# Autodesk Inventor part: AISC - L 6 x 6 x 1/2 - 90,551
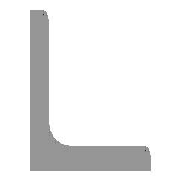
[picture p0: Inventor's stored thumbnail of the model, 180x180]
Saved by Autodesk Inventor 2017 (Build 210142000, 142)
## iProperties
Created: 2016-02
Part Number: AISC - L 6 x 6 x 1/2 - 90,551
Material: Stal, miękka
Description: Kątownik
Document SubType Name: Modeling
Standard: ANSI
Designer: X
Standards Organization: ANSI
Language: pl-PL
Size Designation: L 6 x 6 x 1/2
Categories: <MemberInstance><Categories><Category DisplayName="Kształtowniki konstrukcyjne" InternalName="089c4875-fa83-4c05-b084-43b9cc11f5ed" Mnemonic="GRDR"><CategoryPar
Stock Number: L 6 x 6 x 1/2
Density: 7.85 g/cm^3
Appearance: Częściowo polerowana
_CCFamilyMember: 47
_CCFamilyDisplayName: ANSI L (Kątownik równoramienny) - Kątownik — Rozmiary w nawiasach zostały wycofane
_FrameMemberDoc: Frame Member File
_Version: 15.0.0
_GetPNFromCC: 1
G_L: 2300,000 mm
G_W: 152,400 mm
G_H: 152,400 mm
IsCustomPart: 1
Author: X
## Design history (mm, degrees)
node "Płaszczyzna początkowa"
node "Płaszczyzna końcowa"
sketch "Szkic"
  geometry: L1 (152.4, 0)-(0, 0); L2 (0, 0)-(0, 152.4); L3 (0, 152.4)-(6.35, 152.4); L4 (12.7, 146.05)-(12.7, 25.4); L5 (25.4, 12.7)-(146.05, 12.7); L6 (152.4, 6.35)-(152.4, 0); L7 (0, -11.041)-(0, 31.538); L8 (-11.041, 0)-(31.538, 0); L9 (0, 186.666)-(0, -43.993) reference; L10 (-43.993, 0)-(186.666, 0) reference; A1 r 12.7 centre (25.4, 25.4) between (12.7, 25.4) and (25.4, 12.7); A2 r 6.35 centre (6.35, 146.05) between (12.7, 146.05) and (6.35, 152.4); A3 r 6.35 centre (146.05, 6.35) between (152.4, 6.35) and (146.05, 12.7); 3 further points
  constraints: 16 end point, 6 point on circle, 6 point on line, 6 tangent, 4 parallel, 3 centre point, 2 collinear, 1 equal radius, 1 horizontal, 1 perpendicular
  dimensions: "d0" = 152.4 distance between parallel lines of L6 L2 (= G_H); "d1" = 152.4 distance between parallel lines of L3 L1 (= G_H); "d2" = 12.7 distance between parallel lines of L2 L4 (= G_T); "d3" = 12.7 distance between parallel lines of L1 L5 (= G_T); "d10" = 0 distance between parallel lines of L7 L2 (computed from ex); "d11" = 0 distance between parallel lines of L8 L1 (computed from d10); "d14" = 12.7 radius of A1 (= G_IR); "d15" = 6.35 radius of A2 (= G_ER)
extrude "Bryła" new body sketch "Szkic" stored distance "d4" = 2300 (= G_L); taper "d5" = 0 deg
node "Driven Length"
  sketch "Sketch3"
    geometry: L1 (0, 0)-(10, 0) reference
    constraints: 2 end point, 1 horizontal
  workplane "Work Plane3"
  sketch "Sketch4"
    geometry: L1 (-2, 0)-(12, 0) reference; L2 (-2, 2300)-(12, 2300) reference
    dimensions: "d17" = 2300 distance between parallel lines of L1 L2 (derived)
body "Solid1"
other parameters: "G_H" = 152.4 [user parameter; used in 2 equation terms], "G_T" = 12.7 [user parameter; used in 2 equation terms], "G_ER" = 6.35 [user parameter; used in 1 equation term], "G_IR" = 12.7 [user parameter; used in 1 equation term], "G_L" = 2300 (= d17) [user parameter; used in 1 equation term], "ex" = 0 [user parameter; used in 1 equation term], "G_OFFSET_START" = 0 [user parameter; used in 1 equation term], "G_OFFSET_END" = 0 [user parameter; used in 1 equation term], "d12" = 0 (computed from G_OFFSET_START), "d16" = 90 deg, "MAS" = 2.9168 [user parameter]
